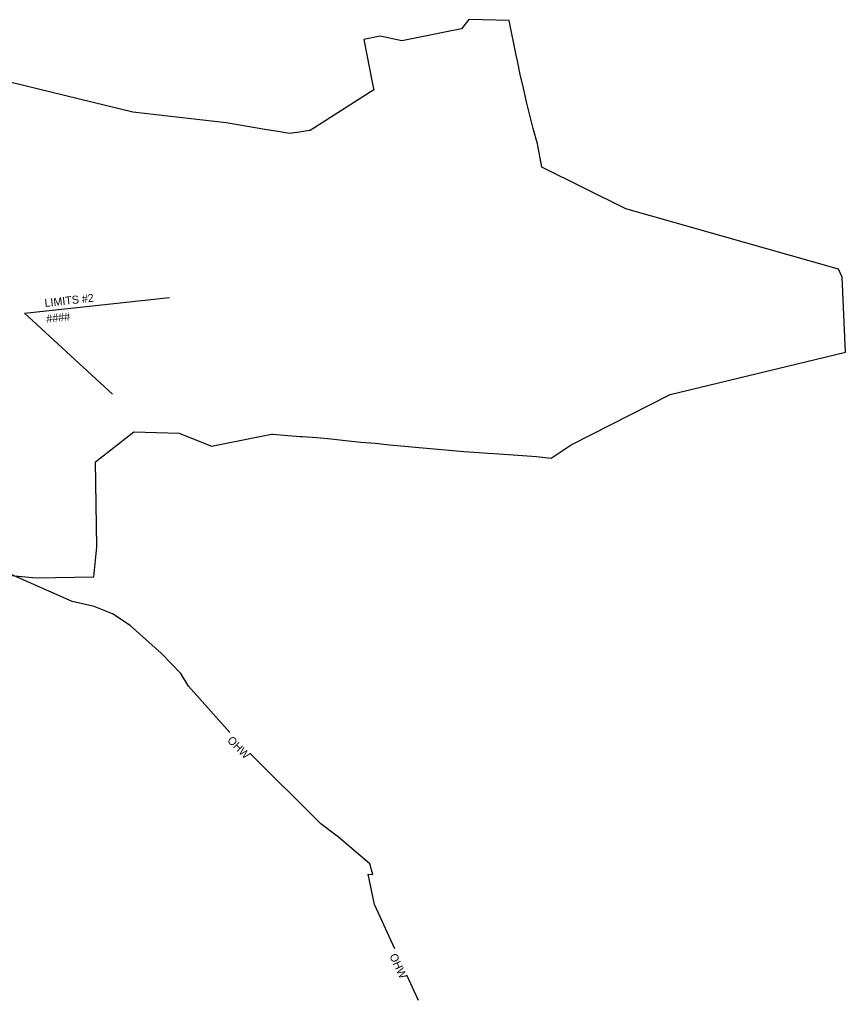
# Model space of a CAD drawing. Extents: x 1509537 to 1510685, y 401169 to 402194.
# Drawn here: x 1510396.5 to 1510685.1, y 401421.5 to 401764.5 of the extents above; entities that cross this region are included whole.
import ezdxf

# ---------------------------------------------------------------- set-up
doc = ezdxf.new("R2010")
doc.units = 0
for name, color, linetype in [('LAWE', 7, 'Continuous'), ('LAWE_P_T', 7, 'Continuous'), ('Level 9', 7, 'Continuous')]:
    doc.layers.add(name, color=color, linetype=linetype)

msp = doc.modelspace()

# ---------------------------------------------------------------- linework, layer by layer
at = {"layer": 'LAWE'}
for points in [[(1510469.91, 401515.23), (1510455.45, 401531.4), (1510452.85, 401535.8), (1510446.06, 401542.82), (1510435.1, 401552.57), (1510428.89, 401556.67), (1510422.58, 401559.27), (1510414.79, 401560.98), (1510390.37, 401571.86)], [(1510527.63, 401439.52), (1510520.48, 401455.02), (1510518.35, 401465.57), (1510519.97, 401465.51), (1510518.87, 401469.21), (1510507.97, 401478.58), (1510501.72, 401483.25), (1510476.99, 401508)], [(1510535.95, 401421.48), (1510531.87, 401430.33)]]:
    msp.add_lwpolyline(points, dxfattribs=at)
at = {"layer": 'LAWE_P_T'}
msp.add_lwpolyline([(1510428.96, 401633.49), (1510398.21, 401661.83), (1510448.81, 401667.34)], dxfattribs=at)
at = {"layer": 'Level 9'}
for points in [[(1510553.49, 401764.52), (1510550.89, 401761.34), (1510530.09, 401757.16), (1510522.48, 401758.69)], [(1510682.71, 401677.22), (1510608.33, 401698.35), (1510578.98, 401712.86), (1510577.55, 401721.05), (1510575.99, 401726.48), (1510574.81, 401731.06), (1510573.67, 401735.77), (1510572.56, 401740.54), (1510571.49, 401745.31), (1510570.47, 401750.08), (1510570.05, 401752.14), (1510567.6, 401764.22), (1510553.49, 401764.52)], [(1510522.48, 401758.69), (1510516.78, 401757.54), (1510519.85, 401742.05), (1510520.27, 401739.91), (1510498.04, 401725.77), (1510497.71, 401725.7), (1510493.48, 401725.03), (1510490.65, 401724.74), (1510487.6, 401725.24), (1510482.88, 401726.02), (1510478.15, 401726.82), (1510473.43, 401727.62), (1510468.72, 401728.44), (1510436.07, 401732.12), (1510364.69, 401749.47)], [(1510685.11, 401648.19), (1510683.94, 401674.39), (1510682.71, 401677.22)], [(1510494.54, 401618.75), (1510495.4, 401618.69), (1510500.41, 401618.31), (1510505.32, 401617.84), (1510510.42, 401617.3), (1510515.7, 401616.77), (1510520.81, 401616.35), (1510525.81, 401615.84), (1510530.97, 401615.32), (1510536.16, 401614.82), (1510541.36, 401614.35), (1510546.57, 401613.91), (1510551.77, 401613.49), (1510556.97, 401613.11), (1510560.1, 401612.89), (1510562.2, 401612.75), (1510567.35, 401612.43), (1510572.29, 401612.11), (1510577.18, 401611.66), (1510582.28, 401611.13), (1510589.3, 401615.77), (1510623.85, 401633.39), (1510685.11, 401648.19)], [(1510264.69, 401617.6), (1510273.34, 401614.89), (1510320.84, 401595.24), (1510341.25, 401595.13), (1510359.26, 401573.21), (1510402.23, 401569.23), (1510422.39, 401569.68), (1510423.42, 401580.07), (1510422.96, 401609.85), (1510436.45, 401620.31), (1510452.26, 401619.93), (1510463.51, 401615.28), (1510484.53, 401619.58)], [(1510484.53, 401619.58), (1510485.01, 401619.53), (1510490.19, 401619.1), (1510493.31, 401618.85), (1510494.54, 401618.75)]]:
    msp.add_lwpolyline(points, dxfattribs=at)

# ---------------------------------------------------------------- texts
at = {"layer": 'LAWE'}
for rotation, p in [(314.6858, (1510468.85, 401512.21)), (294.7624, (1510525.67, 401437.08))]:
    msp.add_text('OHW', height=2.8, rotation=rotation, dxfattribs=at).set_placement(p)
at = {"layer": 'LAWE_P_T'}
for s, p in [('LIMITS #2', (1510405.34, 401664.01)), ('####', (1510405.95, 401658.45))]:
    msp.add_text(s, height=2.8, rotation=6.2219, dxfattribs=at).set_placement(p)

doc.saveas('drawing.dxf')
